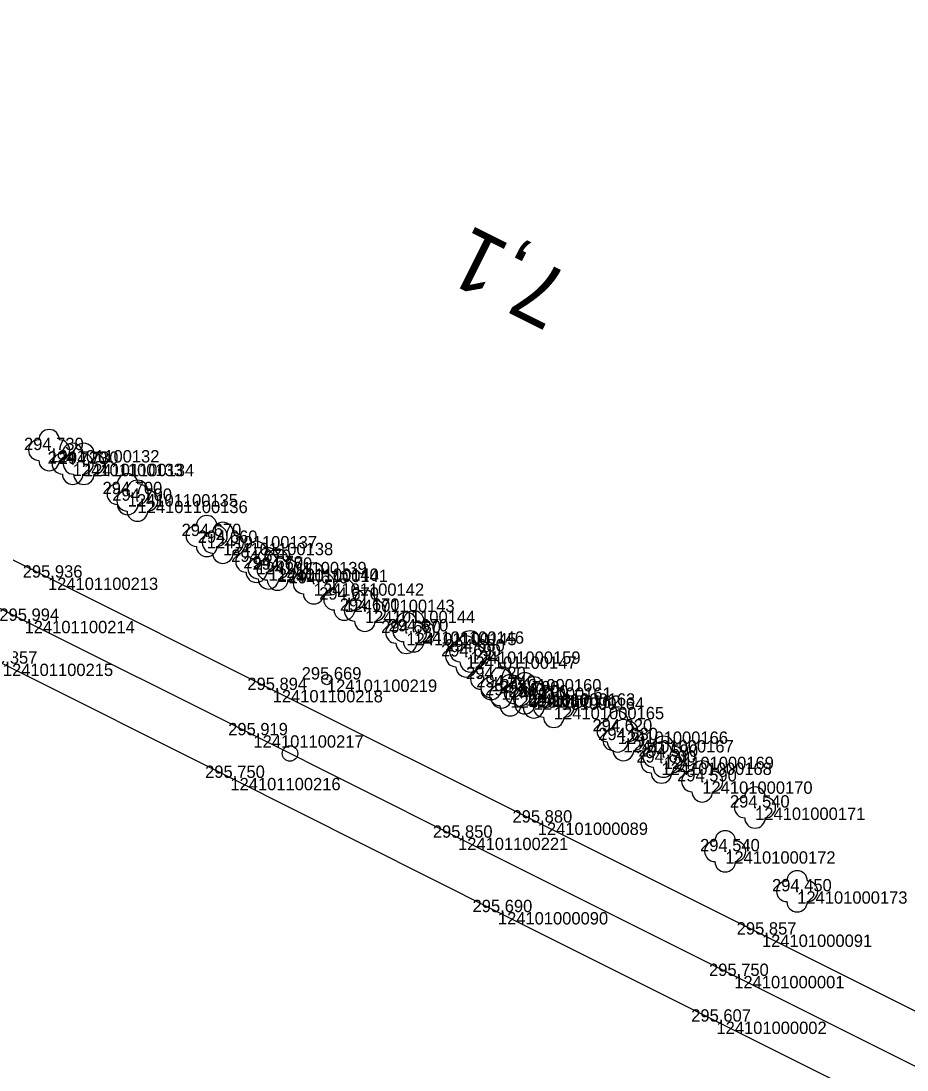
# Model space of a CAD drawing. Extents: x -616949 to -607976, y -1164436 to -1159224.
# Drawn here: x -613443.4 to -613357.3, y -1161463 to -1161361.1 of the extents above; entities that cross this region are included whole.
import ezdxf

# ---------------------------------------------------------------- set-up
doc = ezdxf.new("R2010")
doc.units = 0
for name, color, linetype in [('Vrstva 1', 7, 'Continuous'), ('Vrstva 50', 7, 'Continuous'), ('Vrstva 60', 7, 'Continuous'), ('Vrstva 61', 7, 'Continuous'), ('Vrstva 7', 7, 'Continuous')]:
    doc.layers.add(name, color=color, linetype=linetype)

msp = doc.modelspace()

# ---------------------------------------------------------------- linework, layer by layer
at = {"layer": 'Vrstva 1'}
for points in [[(-613349.94, -1161460.64), (-613371.44, -1161449.88), (-613393.22, -1161439), (-613418.97, -1161426.12), (-613440.8, -1161415.2), (-613460.8, -1161405.2), (-613479.53, -1161395.83), (-613491.4, -1161390.14), (-613492.87, -1161389.47), (-613496.57, -1161387.83), (-613502.72, -1161385.16), (-613510.28, -1161382.03), (-613520.28, -1161378.09), (-613531.28, -1161374.04), (-613546.89, -1161368.42), (-613560.4, -1161361.83), (-613561.83, -1161361.12)], [(-613170.83, -1161560.95), (-613193.86, -1161549.42), (-613216.58, -1161538.05), (-613238.41, -1161527.12), (-613261.08, -1161515.78), (-613282.87, -1161504.88), (-613306.41, -1161493.08), (-613329.58, -1161481.52), (-613354.95, -1161468.79), (-613375.86, -1161458.34), (-613397.09, -1161447.7), (-613423.08, -1161434.66), (-613445.18, -1161423.56), (-613454.31, -1161418.97), (-613455.76, -1161418.24), (-613459.55, -1161416.34), (-613467.93, -1161412.15), (-613475.56, -1161408.23), (-613486.6, -1161402.08), (-613495.53, -1161396.7), (-613502.97, -1161391.95), (-613517.07, -1161383.03), (-613530.57, -1161376.42), (-613531.97, -1161375.72)], [(-613169.01, -1161556.54), (-613191.83, -1161545.12), (-613214.2, -1161533.93), (-613236.35, -1161522.85), (-613258.71, -1161511.65), (-613281.11, -1161500.45), (-613304.08, -1161488.95), (-613327.59, -1161477.18), (-613352.38, -1161464.78), (-613374.13, -1161453.9), (-613400.96, -1161440.47), (-613420.84, -1161430.52), (-613443.07, -1161419.4), (-613460.41, -1161410.77), (-613461.85, -1161410.06), (-613466.23, -1161407.9), (-613484.35, -1161399.03), (-613502.11, -1161390.35), (-613517.07, -1161383.03), (-613530.57, -1161376.42), (-613531.97, -1161375.72)]]:
    msp.add_lwpolyline(points, dxfattribs=at)
at = {"layer": 'Vrstva 50'}
for p, q in [((-613440.75, -1161402.81), (-613440.61, -1161402.81)), ((-613438.46, -1161404.14), (-613438.32, -1161404.14)), ((-613437.37, -1161404.15), (-613437.23, -1161404.15)), ((-613433.12, -1161407.09), (-613432.98, -1161407.09)), ((-613432.17, -1161407.73), (-613432.03, -1161407.73)), ((-613425.44, -1161411.16), (-613425.3, -1161411.16)), ((-613423.87, -1161411.82), (-613423.73, -1161411.82)), ((-613420.62, -1161413.67), (-613420.48, -1161413.67)), ((-613419.44, -1161414.31), (-613419.3, -1161414.31)), ((-613418.55, -1161414.43), (-613418.41, -1161414.43)), ((-613415.04, -1161415.76), (-613414.9, -1161415.76)), ((-613412.07, -1161417.34), (-613411.93, -1161417.34)), ((-613410.07, -1161418.42), (-613409.93, -1161418.42)), ((-613406.05, -1161420.57), (-613405.91, -1161420.57)), ((-613405.33, -1161420.42), (-613405.19, -1161420.42)), ((-613399.84, -1161422.37), (-613399.7, -1161422.37)), ((-613400.23, -1161422.86), (-613400.09, -1161422.86)), ((-613397.81, -1161425.05), (-613397.67, -1161425.05)), ((-613396.81, -1161425.87), (-613396.67, -1161425.87)), ((-613395.95, -1161426.64), (-613395.81, -1161426.64)), ((-613394.53, -1161426.44), (-613394.39, -1161426.44)), ((-613393.67, -1161426.84), (-613393.53, -1161426.84)), ((-613391.72, -1161427.76), (-613391.58, -1161427.76)), ((-613385.52, -1161430.15), (-613385.38, -1161430.15)), ((-613384.96, -1161430.99), (-613384.82, -1161430.99)), ((-613381.06, -1161432.6), (-613380.92, -1161432.6)), ((-613381.26, -1161433.17), (-613381.12, -1161433.17)), ((-613377.3, -1161435), (-613377.16, -1161435)), ((-613372.17, -1161437.54), (-613372.03, -1161437.54)), ((-613375.07, -1161441.79), (-613374.93, -1161441.79)), ((-613368.08, -1161445.68), (-613367.94, -1161445.68))]:
    msp.add_line(p, q, dxfattribs=at)
for centre, start, end in [((-613440.69, -1161401.81), 0, 180), ((-613441.69, -1161402.81), 90, 270), ((-613439.69, -1161402.81), 270, 90), ((-613438.4, -1161403.14), 0, 180), ((-613437.31, -1161403.15), 0, 180), ((-613439.4, -1161404.14), 90, 270), ((-613438.31, -1161404.15), 90, 270), ((-613437.4, -1161404.14), 270, 90), ((-613436.31, -1161404.15), 270, 90), ((-613440.69, -1161403.81), 180, 0), ((-613438.4, -1161405.14), 180, 0), ((-613437.31, -1161405.15), 180, 0), ((-613433.06, -1161406.09), 0, 180), ((-613434.06, -1161407.09), 90, 270), ((-613432.11, -1161406.73), 0, 180), ((-613432.06, -1161407.09), 270, 90), ((-613433.11, -1161407.73), 90, 270), ((-613431.11, -1161407.73), 270, 90), ((-613433.06, -1161408.09), 180, 0), ((-613432.11, -1161408.73), 180, 0), ((-613425.38, -1161410.16), 0, 180), ((-613426.38, -1161411.16), 90, 270), ((-613423.81, -1161410.82), 0, 180), ((-613424.38, -1161411.16), 270, 90), ((-613424.81, -1161411.82), 90, 270), ((-613422.81, -1161411.82), 270, 90), ((-613425.38, -1161412.16), 180, 0), ((-613420.56, -1161412.67), 0, 180), ((-613419.38, -1161413.31), 0, 180), ((-613418.49, -1161413.43), 0, 180), ((-613423.81, -1161412.82), 180, 0), ((-613421.56, -1161413.67), 90, 270), ((-613420.38, -1161414.31), 90, 270), ((-613419.49, -1161414.43), 90, 270), ((-613419.56, -1161413.67), 270, 90), ((-613418.38, -1161414.31), 270, 90), ((-613417.49, -1161414.43), 270, 90), ((-613414.98, -1161414.76), 0, 180), ((-613420.56, -1161414.67), 180, 0), ((-613419.38, -1161415.31), 180, 0), ((-613418.49, -1161415.43), 180, 0), ((-613415.98, -1161415.76), 90, 270), ((-613413.98, -1161415.76), 270, 90), ((-613412.01, -1161416.34), 0, 180), ((-613413.01, -1161417.34), 90, 270), ((-613411.01, -1161417.34), 270, 90), ((-613410.01, -1161417.42), 0, 180), ((-613414.98, -1161416.76), 180, 0), ((-613411.01, -1161418.42), 90, 270), ((-613409.01, -1161418.42), 270, 90), ((-613412.01, -1161418.34), 180, 0), ((-613405.99, -1161419.57), 0, 180), ((-613405.27, -1161419.42), 0, 180), ((-613410.01, -1161419.42), 180, 0), ((-613406.99, -1161420.57), 90, 270), ((-613406.27, -1161420.42), 90, 270), ((-613404.99, -1161420.57), 270, 90), ((-613404.27, -1161420.42), 270, 90), ((-613399.78, -1161421.37), 0, 180), ((-613405.99, -1161421.57), 180, 0), ((-613405.27, -1161421.42), 180, 0), ((-613400.78, -1161422.37), 90, 270), ((-613400.17, -1161421.86), 0, 180), ((-613398.78, -1161422.37), 270, 90), ((-613401.17, -1161422.86), 90, 270), ((-613399.17, -1161422.86), 270, 90), ((-613399.78, -1161423.37), 180, 0), ((-613397.75, -1161424.05), 0, 180), ((-613400.17, -1161423.86), 180, 0), ((-613398.75, -1161425.05), 90, 270), ((-613396.75, -1161424.87), 0, 180), ((-613395.89, -1161425.64), 0, 180), ((-613396.75, -1161425.05), 270, 90), ((-613394.47, -1161425.44), 0, 180), ((-613397.75, -1161425.87), 90, 270), ((-613396.89, -1161426.64), 90, 270), ((-613395.47, -1161426.44), 90, 270), ((-613395.75, -1161425.87), 270, 90), ((-613394.89, -1161426.64), 270, 90), ((-613393.61, -1161425.84), 0, 180), ((-613393.47, -1161426.44), 270, 90), ((-613391.66, -1161426.76), 0, 180), ((-613397.75, -1161426.05), 180, 0), ((-613394.61, -1161426.84), 90, 270), ((-613392.66, -1161427.76), 90, 270), ((-613392.61, -1161426.84), 270, 90), ((-613390.66, -1161427.76), 270, 90), ((-613396.75, -1161426.87), 180, 0), ((-613395.89, -1161427.64), 180, 0), ((-613394.47, -1161427.44), 180, 0), ((-613393.61, -1161427.84), 180, 0), ((-613391.66, -1161428.76), 180, 0), ((-613385.46, -1161429.15), 0, 180), ((-613386.46, -1161430.15), 90, 270), ((-613384.9, -1161429.99), 0, 180), ((-613384.46, -1161430.15), 270, 90), ((-613385.9, -1161430.99), 90, 270), ((-613383.9, -1161430.99), 270, 90), ((-613381, -1161431.6), 0, 180), ((-613385.46, -1161431.15), 180, 0), ((-613382, -1161432.6), 90, 270), ((-613381.2, -1161432.17), 0, 180), ((-613380, -1161432.6), 270, 90), ((-613384.9, -1161431.99), 180, 0), ((-613382.2, -1161433.17), 90, 270), ((-613380.2, -1161433.17), 270, 90), ((-613381, -1161433.6), 180, 0), ((-613377.24, -1161434), 0, 180), ((-613381.2, -1161434.17), 180, 0), ((-613378.24, -1161435), 90, 270), ((-613376.24, -1161435), 270, 90), ((-613377.24, -1161436), 180, 0), ((-613372.11, -1161436.54), 0, 180), ((-613373.11, -1161437.54), 90, 270), ((-613371.11, -1161437.54), 270, 90), ((-613372.11, -1161438.54), 180, 0), ((-613375.01, -1161440.79), 0, 180), ((-613376.01, -1161441.79), 90, 270), ((-613374.01, -1161441.79), 270, 90), ((-613375.01, -1161442.79), 180, 0), ((-613368.02, -1161444.68), 0, 180), ((-613369.02, -1161445.68), 90, 270), ((-613367.02, -1161445.68), 270, 90), ((-613368.02, -1161446.68), 180, 0)]:
    msp.add_arc(centre, 1, start, end, dxfattribs=at)
at = {"layer": 'Vrstva 60'}
for p, q in [((-613440.68, -1161402.81), (-613440.68, -1161402.81)), ((-613438.39, -1161404.14), (-613438.39, -1161404.14)), ((-613437.3, -1161404.15), (-613437.3, -1161404.15)), ((-613433.05, -1161407.09), (-613433.05, -1161407.09)), ((-613432.1, -1161407.73), (-613432.1, -1161407.73)), ((-613425.37, -1161411.16), (-613425.37, -1161411.16)), ((-613423.8, -1161411.82), (-613423.8, -1161411.82)), ((-613420.55, -1161413.67), (-613420.55, -1161413.67)), ((-613419.37, -1161414.31), (-613419.37, -1161414.31)), ((-613418.48, -1161414.43), (-613418.48, -1161414.43)), ((-613440.8, -1161415.2), (-613440.8, -1161415.2)), ((-613414.97, -1161415.76), (-613414.97, -1161415.76)), ((-613412, -1161417.34), (-613412, -1161417.34)), ((-613410, -1161418.42), (-613410, -1161418.42)), ((-613443.07, -1161419.4), (-613443.07, -1161419.4)), ((-613405.98, -1161420.57), (-613405.98, -1161420.57)), ((-613405.26, -1161420.42), (-613405.26, -1161420.42)), ((-613399.77, -1161422.37), (-613399.77, -1161422.37)), ((-613400.16, -1161422.86), (-613400.16, -1161422.86)), ((-613413.7, -1161425.1), (-613413.7, -1161425.1)), ((-613397.74, -1161425.05), (-613397.74, -1161425.05)), ((-613418.97, -1161426.12), (-613418.97, -1161426.12)), ((-613396.74, -1161425.87), (-613396.74, -1161425.87)), ((-613395.88, -1161426.64), (-613395.88, -1161426.64)), ((-613394.46, -1161426.44), (-613394.46, -1161426.44)), ((-613393.6, -1161426.84), (-613393.6, -1161426.84)), ((-613391.65, -1161427.76), (-613391.65, -1161427.76)), ((-613420.84, -1161430.52), (-613420.84, -1161430.52)), ((-613385.45, -1161430.15), (-613385.45, -1161430.15)), ((-613384.89, -1161430.99), (-613384.89, -1161430.99)), ((-613380.99, -1161432.6), (-613380.99, -1161432.6)), ((-613381.19, -1161433.17), (-613381.19, -1161433.17)), ((-613423.08, -1161434.66), (-613423.08, -1161434.66)), ((-613377.23, -1161435), (-613377.23, -1161435)), ((-613372.1, -1161437.54), (-613372.1, -1161437.54)), ((-613393.22, -1161439), (-613393.22, -1161439)), ((-613400.96, -1161440.47), (-613400.96, -1161440.47)), ((-613375, -1161441.79), (-613375, -1161441.79)), ((-613368.01, -1161445.68), (-613368.01, -1161445.68)), ((-613397.09, -1161447.7), (-613397.09, -1161447.7)), ((-613371.44, -1161449.88), (-613371.44, -1161449.88)), ((-613374.13, -1161453.9), (-613374.13, -1161453.9)), ((-613375.86, -1161458.34), (-613375.86, -1161458.34))]:
    msp.add_line(p, q, dxfattribs=at)
at = {"layer": 'Vrstva 7'}
msp.add_line((-613413.65, -1161425.12), (-613413.74, -1161425.08), dxfattribs=at)
for centre, radius in [((-613413.7, -1161425.1), 0.5), ((-613417.29, -1161432.29), 0.75)]:
    msp.add_circle(centre, radius, dxfattribs=at)

# ---------------------------------------------------------------- texts
at = {"layer": 'Vrstva 60'}
for s, p in [('124101100132', (-613440.68, -1161404.01)), ('124101100133', (-613438.39, -1161405.34)), ('124101100134', (-613437.3, -1161405.35)), ('124101100135', (-613433.05, -1161408.29)), ('124101100136', (-613432.1, -1161408.93)), ('124101100137', (-613425.37, -1161412.36)), ('124101100138', (-613423.8, -1161413.02)), ('124101100139', (-613420.55, -1161414.87)), ('124101100140', (-613419.37, -1161415.51)), ('124101100141', (-613418.48, -1161415.63)), ('124101100213', (-613440.8, -1161416.4)), ('124101100142', (-613414.97, -1161416.96)), ('124101100143', (-613412, -1161418.54)), ('124101100144', (-613410, -1161419.62)), ('124101100214', (-613443.07, -1161420.6)), ('124101100145', (-613405.98, -1161421.77)), ('124101100146', (-613405.26, -1161421.62)), ('124101000159', (-613399.77, -1161423.57)), ('124101100215', (-613445.18, -1161424.76)), ('124101100147', (-613400.16, -1161424.06)), ('124101100219', (-613413.7, -1161426.3)), ('124101000160', (-613397.74, -1161426.25)), ('124101100218', (-613418.97, -1161427.32)), ('124101000161', (-613396.74, -1161427.07)), ('124101000162', (-613395.88, -1161427.84)), ('124101000163', (-613394.46, -1161427.64)), ('124101000164', (-613393.6, -1161428.04)), ('124101000165', (-613391.65, -1161428.96)), ('124101100217', (-613420.84, -1161431.72)), ('124101000166', (-613385.45, -1161431.35)), ('124101000167', (-613384.89, -1161432.19)), ('124101000169', (-613380.99, -1161433.8)), ('124101000168', (-613381.19, -1161434.37)), ('124101100216', (-613423.08, -1161435.86)), ('124101000170', (-613377.23, -1161436.2)), ('124101000171', (-613372.1, -1161438.74)), ('124101000089', (-613393.22, -1161440.2)), ('124101100221', (-613400.96, -1161441.67)), ('124101000172', (-613375, -1161442.99)), ('124101000173', (-613368.01, -1161446.88)), ('124101000090', (-613397.09, -1161448.9)), ('124101000091', (-613371.44, -1161451.08)), ('124101000001', (-613374.13, -1161455.1)), ('124101000002', (-613375.86, -1161459.54))]:
    msp.add_text(s, height=1.2, dxfattribs=at).set_placement(p)
at = {"layer": 'Vrstva 61'}
for s, p in [('294.730', (-613443.13, -1161402.81)), ('294.720', (-613440.84, -1161404.14)), ('294.730', (-613439.75, -1161404.15)), ('294.700', (-613435.5, -1161407.09)), ('294.700', (-613434.55, -1161407.73)), ('294.670', (-613427.82, -1161411.16)), ('294.660', (-613426.25, -1161411.82)), ('294.670', (-613423, -1161413.67)), ('294.670', (-613421.82, -1161414.31)), ('294.670', (-613420.93, -1161414.43)), ('295.936', (-613443.25, -1161415.2)), ('294.670', (-613417.42, -1161415.76)), ('294.670', (-613414.45, -1161417.34)), ('294.670', (-613412.45, -1161418.42)), ('295.994', (-613445.52, -1161419.4)), ('294.680', (-613408.43, -1161420.57)), ('294.670', (-613407.71, -1161420.42)), ('294.690', (-613402.61, -1161422.86)), ('294.680', (-613402.22, -1161422.37)), ('295.857', (-613447.63, -1161423.56)), ('295.669', (-613416.15, -1161425.1)), ('294.720', (-613400.19, -1161425.05)), ('294.740', (-613399.19, -1161425.87)), ('295.894', (-613421.43, -1161426.12)), ('294.740', (-613398.33, -1161426.64)), ('294.700', (-613396.91, -1161426.44)), ('294.700', (-613396.05, -1161426.84)), ('294.680', (-613394.1, -1161427.76)), ('295.919', (-613423.29, -1161430.52)), ('294.620', (-613387.9, -1161430.15)), ('294.630', (-613387.34, -1161430.99)), ('294.590', (-613383.44, -1161432.6)), ('294.600', (-613383.64, -1161433.17)), ('295.750', (-613425.53, -1161434.66)), ('294.590', (-613379.68, -1161435)), ('294.540', (-613374.55, -1161437.54)), ('295.880', (-613395.67, -1161439)), ('295.850', (-613403.41, -1161440.47)), ('294.540', (-613377.45, -1161441.79)), ('294.450', (-613370.46, -1161445.68)), ('295.690', (-613399.55, -1161447.7)), ('295.857', (-613373.89, -1161449.88)), ('295.750', (-613376.58, -1161453.9)), ('295.607', (-613378.31, -1161458.34))]:
    msp.add_text(s, height=1.2, dxfattribs=at).set_placement(p)
at = {"layer": 'Vrstva 7'}
msp.add_text('7,1', height=6, rotation=153.3946, dxfattribs=at).set_placement((-613389.69, -1161385.95))

doc.saveas('drawing.dxf')
